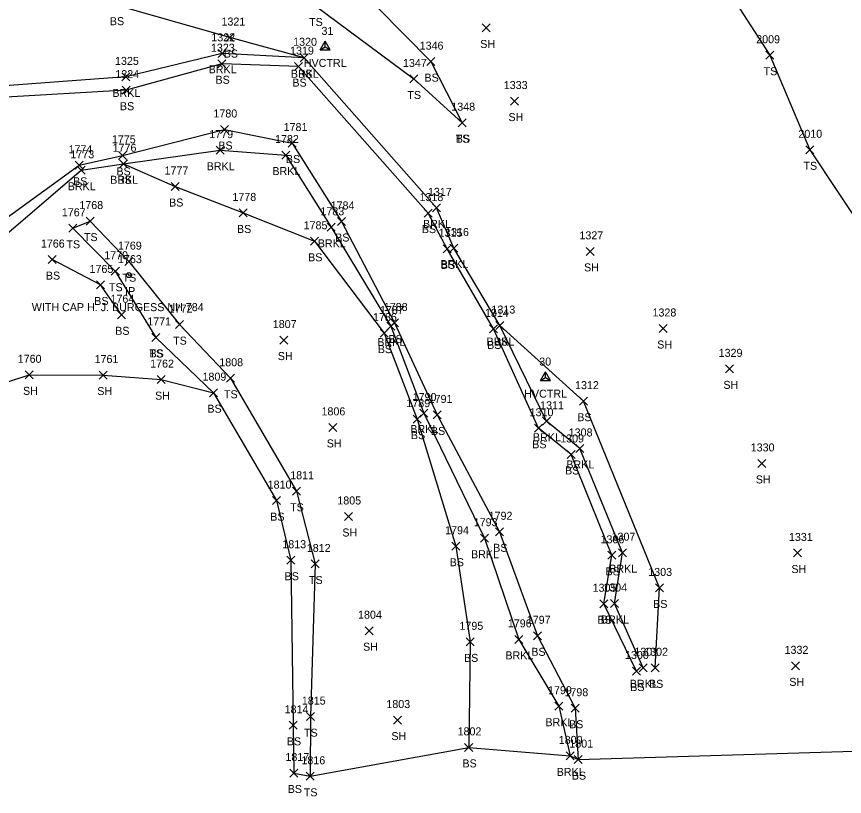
# Model space of a CAD drawing. Extents: x 1754529 to 1755810, y 621660 to 624656.
# Drawn here: x 1755214.3 to 1755421.2, y 623759.8 to 623954.6 of the extents above; entities that cross this region are included whole.
import ezdxf

# ---------------------------------------------------------------- set-up
doc = ezdxf.new("R2010")
doc.units = 0
for name, color, linetype in [('C_A', 7, 'Continuous'), ('C_I', 7, 'Continuous'), ('CPSM', 7, 'Continuous'), ('L_A', 7, 'Continuous'), ('L_I', 7, 'Continuous'), ('L_TIC', 7, 'Continuous'), ('LAWE', 7, 'Continuous'), ('LELB', 7, 'Continuous'), ('LSOGP', 7, 'Continuous'), ('M_A', 7, 'Continuous'), ('M_C', 7, 'Continuous'), ('M_I', 7, 'Continuous'), ('MPIR', 7, 'Continuous')]:
    doc.layers.add(name, color=color, linetype=linetype)

msp = doc.modelspace()

# ---------------------------------------------------------------- linework, layer by layer
at = {"layer": 'CPSM'}
for p, q in [((1755290.13, 623946.27), (1755291.38, 623948.44)), ((1755292.63, 623946.27), (1755291.38, 623948.44)), ((1755291.38, 623947), (1755291.38, 623948.44)), ((1755290.13, 623946.27), (1755291.38, 623947)), ((1755290.13, 623946.27), (1755292.63, 623946.27)), ((1755291.38, 623947), (1755291.38, 623947)), ((1755291.38, 623947), (1755292.63, 623946.27)), ((1755345.2, 623863.69), (1755346.45, 623865.86)), ((1755345.2, 623863.69), (1755346.45, 623864.41)), ((1755347.7, 623863.69), (1755346.45, 623865.86)), ((1755346.45, 623864.41), (1755346.45, 623865.86)), ((1755346.45, 623864.41), (1755346.45, 623864.41)), ((1755346.45, 623864.41), (1755347.7, 623863.69)), ((1755345.2, 623863.69), (1755347.7, 623863.69))]:
    msp.add_line(p, q, dxfattribs=at)
at = {"layer": 'L_TIC'}
for points in [[(1755330.68, 623950.74), (1755332.68, 623952.74)], [(1755332.68, 623950.74), (1755330.68, 623952.74)], [(1755266.63, 623948.34), (1755268.63, 623950.34)], [(1755268.63, 623948.34), (1755266.63, 623950.34)], [(1755264.65, 623944.4), (1755266.65, 623946.4)], [(1755266.65, 623944.4), (1755264.65, 623946.4)], [(1755285.2, 623943.29), (1755287.2, 623945.29)], [(1755287.2, 623943.29), (1755285.2, 623945.29)], [(1755285.2, 623943.29), (1755287.2, 623945.29)], [(1755287.2, 623943.29), (1755285.2, 623945.29)], [(1755401.54, 623943.92), (1755403.54, 623945.92)], [(1755403.54, 623943.92), (1755401.54, 623945.92)], [(1755264.57, 623941.8), (1755266.57, 623943.8)], [(1755266.57, 623941.8), (1755264.57, 623943.8)], [(1755283.78, 623941.09), (1755285.78, 623943.09)], [(1755285.78, 623941.09), (1755283.78, 623943.09)], [(1755316.78, 623942.33), (1755318.78, 623944.33)], [(1755318.78, 623942.33), (1755316.78, 623944.33)], [(1755240.6, 623938.51), (1755242.6, 623940.51)], [(1755242.6, 623938.51), (1755240.6, 623940.51)], [(1755312.55, 623938), (1755314.55, 623940)], [(1755314.55, 623938), (1755312.55, 623940)], [(1755240.68, 623935.2), (1755242.68, 623937.2)], [(1755242.68, 623935.2), (1755240.68, 623937.2)], [(1755337.73, 623932.48), (1755339.73, 623934.48)], [(1755339.73, 623932.48), (1755337.73, 623934.48)], [(1755324.62, 623927.08), (1755326.62, 623929.08)], [(1755326.62, 623927.08), (1755324.62, 623929.08)], [(1755324.62, 623927.08), (1755326.62, 623929.08)], [(1755326.62, 623927.08), (1755324.62, 623929.08)], [(1755265.28, 623925.38), (1755267.28, 623927.38)], [(1755267.28, 623925.38), (1755265.28, 623927.38)], [(1755264.16, 623920.22), (1755266.16, 623922.22)], [(1755266.16, 623920.22), (1755264.16, 623922.22)], [(1755282.17, 623922), (1755284.17, 623924)], [(1755284.17, 623922), (1755282.17, 623924)], [(1755411.5, 623920.31), (1755413.5, 623922.31)], [(1755413.5, 623920.31), (1755411.5, 623922.31)], [(1755239.82, 623918.92), (1755241.82, 623920.92)], [(1755241.82, 623918.92), (1755239.82, 623920.92)], [(1755280.59, 623919), (1755282.59, 623921)], [(1755282.59, 623919), (1755280.59, 623921)], [(1755228.99, 623916.44), (1755230.99, 623918.44)], [(1755230.99, 623916.44), (1755228.99, 623918.44)], [(1755240.06, 623916.82), (1755242.06, 623918.82)], [(1755242.06, 623916.82), (1755240.06, 623918.82)], [(1755240.06, 623916.82), (1755242.06, 623918.82)], [(1755242.06, 623916.82), (1755240.06, 623918.82)], [(1755229.46, 623915.2), (1755231.46, 623917.2)], [(1755231.46, 623915.2), (1755229.46, 623917.2)], [(1755252.98, 623911.14), (1755254.98, 623913.14)], [(1755254.98, 623911.14), (1755252.98, 623913.14)], [(1755318.21, 623905.81), (1755320.21, 623907.81)], [(1755320.21, 623905.81), (1755318.21, 623907.81)], [(1755269.94, 623904.54), (1755271.94, 623906.54)], [(1755271.94, 623904.54), (1755269.94, 623906.54)], [(1755316.12, 623904.5), (1755318.12, 623906.5)], [(1755318.12, 623904.5), (1755316.12, 623906.5)], [(1755231.74, 623902.51), (1755233.74, 623904.51)], [(1755233.74, 623902.51), (1755231.74, 623904.51)], [(1755294.47, 623902.4), (1755296.47, 623904.4)], [(1755296.47, 623902.4), (1755294.47, 623904.4)], [(1755227.36, 623900.7), (1755229.36, 623902.7)], [(1755229.36, 623900.7), (1755227.36, 623902.7)], [(1755227.36, 623900.7), (1755229.36, 623902.7)], [(1755229.36, 623900.7), (1755227.36, 623902.7)], [(1755291.93, 623900.95), (1755293.93, 623902.95)], [(1755293.93, 623900.95), (1755291.93, 623902.95)], [(1755287.72, 623897.46), (1755289.72, 623899.46)], [(1755289.72, 623897.46), (1755287.72, 623899.46)], [(1755320.88, 623895.58), (1755322.88, 623897.58)], [(1755322.88, 623895.58), (1755320.88, 623897.58)], [(1755322.56, 623895.77), (1755324.56, 623897.77)], [(1755324.56, 623895.77), (1755322.56, 623897.77)], [(1755356.63, 623894.94), (1755358.63, 623896.94)], [(1755358.63, 623894.94), (1755356.63, 623896.94)], [(1755222.19, 623892.89), (1755224.19, 623894.89)], [(1755224.19, 623892.89), (1755222.19, 623894.89)], [(1755241.39, 623892.38), (1755243.39, 623894.38)], [(1755243.39, 623892.38), (1755241.39, 623894.38)], [(1755237.99, 623889.98), (1755239.99, 623891.98)], [(1755239.99, 623889.98), (1755237.99, 623891.98)], [(1755234.28, 623886.55), (1755236.28, 623888.55)], [(1755236.28, 623886.55), (1755234.28, 623888.55)], [(1755239.52, 623879.1), (1755241.52, 623881.1)], [(1755241.52, 623879.1), (1755239.52, 623881.1)], [(1755307.77, 623877.06), (1755309.77, 623879.06)], [(1755309.77, 623877.06), (1755307.77, 623879.06)], [(1755254.02, 623876.65), (1755256.02, 623878.65)], [(1755256.02, 623876.65), (1755254.02, 623878.65)], [(1755306.79, 623876.29), (1755308.79, 623878.29)], [(1755308.79, 623876.29), (1755306.79, 623878.29)], [(1755332.45, 623875.59), (1755334.45, 623877.59)], [(1755334.45, 623875.59), (1755332.45, 623877.59)], [(1755334.09, 623876.41), (1755336.09, 623878.41)], [(1755336.09, 623876.41), (1755334.09, 623878.41)], [(1755334.09, 623876.41), (1755336.09, 623878.41)], [(1755336.09, 623876.41), (1755334.09, 623878.41)], [(1755374.89, 623875.68), (1755376.89, 623877.68)], [(1755376.89, 623875.68), (1755374.89, 623877.68)], [(1755248.09, 623873.44), (1755250.09, 623875.44)], [(1755250.09, 623873.44), (1755248.09, 623875.44)], [(1755248.09, 623873.44), (1755250.09, 623875.44)], [(1755250.09, 623873.44), (1755248.09, 623875.44)], [(1755280.1, 623872.79), (1755282.1, 623874.79)], [(1755282.1, 623872.79), (1755280.1, 623874.79)], [(1755305.12, 623874.52), (1755307.12, 623876.52)], [(1755307.12, 623874.52), (1755305.12, 623876.52)], [(1755391.43, 623865.6), (1755393.43, 623867.6)], [(1755393.43, 623865.6), (1755391.43, 623867.6)], [(1755216.43, 623864.11), (1755218.43, 623866.11)], [(1755218.43, 623864.11), (1755216.43, 623866.11)], [(1755234.99, 623864.05), (1755236.99, 623866.05)], [(1755236.99, 623864.05), (1755234.99, 623866.05)], [(1755249.43, 623862.91), (1755251.43, 623864.91)], [(1755251.43, 623862.91), (1755249.43, 623864.91)], [(1755266.73, 623863.25), (1755268.73, 623865.25)], [(1755268.73, 623863.25), (1755266.73, 623865.25)], [(1755262.55, 623859.65), (1755264.55, 623861.65)], [(1755264.55, 623859.65), (1755262.55, 623861.65)], [(1755354.97, 623857.53), (1755356.97, 623859.53)], [(1755356.97, 623857.53), (1755354.97, 623859.53)], [(1755315.06, 623854.57), (1755317.06, 623856.57)], [(1755317.06, 623854.57), (1755315.06, 623856.57)], [(1755318.4, 623854.09), (1755320.4, 623856.09)], [(1755320.4, 623854.09), (1755318.4, 623856.09)], [(1755313.4, 623853.04), (1755315.4, 623855.04)], [(1755315.4, 623853.04), (1755313.4, 623855.04)], [(1755345.68, 623852.51), (1755347.68, 623854.51)], [(1755347.68, 623852.51), (1755345.68, 623854.51)], [(1755292.32, 623850.98), (1755294.32, 623852.98)], [(1755294.32, 623850.98), (1755292.32, 623852.98)], [(1755343.71, 623850.76), (1755345.71, 623852.76)], [(1755345.71, 623850.76), (1755343.71, 623852.76)], [(1755351.91, 623844.22), (1755353.91, 623846.22)], [(1755353.91, 623844.22), (1755351.91, 623846.22)], [(1755354.03, 623845.72), (1755356.03, 623847.72)], [(1755356.03, 623845.72), (1755354.03, 623847.72)], [(1755399.52, 623841.98), (1755401.52, 623843.98)], [(1755401.52, 623841.98), (1755399.52, 623843.98)], [(1755283.24, 623835.03), (1755285.24, 623837.03)], [(1755285.24, 623835.03), (1755283.24, 623837.03)], [(1755278.26, 623832.69), (1755280.26, 623834.69)], [(1755280.26, 623832.69), (1755278.26, 623834.69)], [(1755296.23, 623828.73), (1755298.23, 623830.73)], [(1755298.23, 623828.73), (1755296.23, 623830.73)], [(1755330.23, 623823.3), (1755332.23, 623825.3)], [(1755332.23, 623823.3), (1755330.23, 623825.3)], [(1755333.96, 623824.91), (1755335.96, 623826.91)], [(1755335.96, 623824.91), (1755333.96, 623826.91)], [(1755323.08, 623821.3), (1755325.08, 623823.3)], [(1755325.08, 623821.3), (1755323.08, 623823.3)], [(1755362.04, 623819.03), (1755364.04, 623821.03)], [(1755364.04, 623819.03), (1755362.04, 623821.03)], [(1755364.74, 623819.69), (1755366.74, 623821.69)], [(1755366.74, 623819.69), (1755364.74, 623821.69)], [(1755408.41, 623819.61), (1755410.41, 623821.61)], [(1755410.41, 623819.61), (1755408.41, 623821.61)], [(1755281.84, 623817.8), (1755283.84, 623819.8)], [(1755283.84, 623817.8), (1755281.84, 623819.8)], [(1755287.95, 623816.87), (1755289.95, 623818.87)], [(1755289.95, 623816.87), (1755287.95, 623818.87)], [(1755373.92, 623810.88), (1755375.92, 623812.88)], [(1755375.92, 623810.88), (1755373.92, 623812.88)], [(1755360.01, 623806.93), (1755362.01, 623808.93)], [(1755362.01, 623806.93), (1755360.01, 623808.93)], [(1755362.68, 623807), (1755364.68, 623809)], [(1755364.68, 623807), (1755362.68, 623809)], [(1755301.4, 623800.2), (1755303.4, 623802.2)], [(1755303.4, 623800.2), (1755301.4, 623802.2)], [(1755343.48, 623798.93), (1755345.48, 623800.93)], [(1755345.48, 623798.93), (1755343.48, 623800.93)], [(1755326.66, 623797.42), (1755328.66, 623799.42)], [(1755328.66, 623797.42), (1755326.66, 623799.42)], [(1755338.8, 623798.04), (1755340.8, 623800.04)], [(1755340.8, 623798.04), (1755338.8, 623800.04)], [(1755368.19, 623790.13), (1755370.19, 623792.13)], [(1755370.19, 623790.13), (1755368.19, 623792.13)], [(1755369.87, 623790.95), (1755371.87, 623792.95)], [(1755371.87, 623790.95), (1755369.87, 623792.95)], [(1755372.89, 623790.94), (1755374.89, 623792.94)], [(1755374.89, 623790.94), (1755372.89, 623792.94)], [(1755407.89, 623791.42), (1755409.89, 623793.42)], [(1755409.89, 623791.42), (1755407.89, 623793.42)], [(1755348.8, 623781.35), (1755350.8, 623783.35)], [(1755350.8, 623781.35), (1755348.8, 623783.35)], [(1755352.9, 623780.84), (1755354.9, 623782.84)], [(1755354.9, 623780.84), (1755352.9, 623782.84)], [(1755286.72, 623778.74), (1755288.72, 623780.74)], [(1755288.72, 623778.74), (1755286.72, 623780.74)], [(1755308.48, 623777.88), (1755310.48, 623779.88)], [(1755310.48, 623777.88), (1755308.48, 623779.88)], [(1755282.41, 623776.57), (1755284.41, 623778.57)], [(1755284.41, 623776.57), (1755282.41, 623778.57)], [(1755326.27, 623771.06), (1755328.27, 623773.06)], [(1755328.27, 623771.06), (1755326.27, 623773.06)], [(1755351.63, 623768.93), (1755353.63, 623770.93)], [(1755353.63, 623768.93), (1755351.63, 623770.93)], [(1755353.61, 623768.01), (1755355.61, 623770.01)], [(1755355.61, 623768.01), (1755353.61, 623770.01)], [(1755282.62, 623764.66), (1755284.62, 623766.66)], [(1755284.62, 623764.66), (1755282.62, 623766.66)], [(1755286.66, 623763.84), (1755288.66, 623765.84)], [(1755288.66, 623763.84), (1755286.66, 623765.84)]]:
    msp.add_lwpolyline(points, dxfattribs=at)
at = {"layer": 'LAWE'}
for points in [[(1755370.87, 623791.95), (1755363.68, 623808), (1755365.74, 623820.69), (1755355.03, 623846.72), (1755346.68, 623853.51), (1755335.09, 623877.41), (1755323.56, 623896.77), (1755319.21, 623906.81), (1755286.2, 623944.29), (1755265.65, 623945.4), (1755241.6, 623939.51), (1755210.27, 623937.23), (1755179.93, 623958.52)], [(1755204.82, 623894.29), (1755230.46, 623916.2), (1755241.06, 623917.82), (1755265.16, 623921.22), (1755281.59, 623920), (1755292.93, 623901.95), (1755307.79, 623877.29), (1755316.06, 623855.57), (1755331.23, 623824.3), (1755339.8, 623799.04), (1755349.8, 623782.35), (1755352.63, 623769.93)]]:
    msp.add_lwpolyline(points, dxfattribs=at)
at = {"layer": 'LELB'}
for points in [[(1755283.63, 624321.58), (1755261.89, 624310.21), (1755241.28, 624298.92), (1755225.63, 624290.24), (1755219.57, 624277.64), (1755236.29, 624268.09), (1755239.17, 624251.56), (1755235.61, 624235.54), (1755253.41, 624214.52), (1755275.93, 624188.95), (1755280.26, 624179.83), (1755294.83, 624178.69), (1755307.15, 624169.54), (1755309.03, 624155.09), (1755307.67, 624133.57), (1755296.24, 624106.15), (1755299.26, 624064.9), (1755318.78, 624037.89), (1755344, 624017.13), (1755370, 623994.13), (1755389.34, 623965.32), (1755402.54, 623944.92), (1755412.5, 623921.31), (1755426.67, 623899.96)], [(1755286.2, 623944.29), (1755267.63, 623949.34), (1755239.18, 623957.43), (1755232.04, 623971.1), (1755221.75, 623997.22), (1755207.57, 624028.22), (1755193.15, 624052.21), (1755209.59, 624065.41), (1755204.71, 624097.4), (1755197.92, 624122.33)], [(1755249.6, 623996.64), (1755238.46, 623980.5), (1755248.16, 623968.47), (1755260.84, 623963.41), (1755288.99, 623957.23), (1755313.55, 623939), (1755325.62, 623928.08)], [(1755249.6, 623996.64), (1755264.38, 623977.8), (1755286.06, 623972.14), (1755297.89, 623963.61), (1755317.78, 623943.33), (1755325.62, 623928.08)], [(1755369.19, 623791.13), (1755361.01, 623807.93), (1755363.04, 623820.03), (1755352.91, 623845.22), (1755344.71, 623851.76), (1755333.45, 623876.59), (1755321.88, 623896.58), (1755317.12, 623905.5), (1755284.78, 623942.09), (1755265.57, 623942.8), (1755241.68, 623936.2), (1755210.26, 623934.38)], [(1755204.31, 623898.91), (1755229.99, 623917.44), (1755240.82, 623919.92), (1755266.28, 623926.38), (1755283.17, 623923), (1755295.47, 623903.4), (1755308.77, 623878.06), (1755319.4, 623855.09), (1755334.96, 623825.91), (1755344.48, 623799.93), (1755353.9, 623781.84), (1755354.61, 623769.01)], [(1755241.06, 623917.82), (1755253.98, 623912.14), (1755270.94, 623905.54), (1755288.72, 623898.46), (1755306.12, 623875.52), (1755314.4, 623854.04), (1755324.08, 623822.3), (1755327.66, 623798.42), (1755327.27, 623772.06)], [(1755228.36, 623901.7), (1755232.74, 623903.51), (1755242.39, 623893.38), (1755255.02, 623877.65), (1755267.73, 623864.25), (1755284.24, 623836.03), (1755288.95, 623817.87), (1755287.72, 623779.74), (1755287.66, 623764.84)], [(1755228.36, 623901.7), (1755238.99, 623890.98), (1755249.09, 623874.44)], [(1755240.52, 623880.1), (1755235.28, 623887.55), (1755223.19, 623893.89)], [(1755373.89, 623791.94), (1755374.92, 623811.88), (1755355.97, 623858.53), (1755335.09, 623877.41)], [(1755249.09, 623874.44), (1755263.55, 623860.65), (1755279.26, 623833.69), (1755282.84, 623818.8), (1755283.41, 623777.57), (1755283.62, 623765.66)]]:
    msp.add_lwpolyline(points, dxfattribs=at)
at = {"layer": 'LSOGP'}
msp.add_lwpolyline([(1755004.07, 623910.86), (1755037.03, 623891.65), (1755051.38, 623882.08), (1755070.03, 623866.74), (1755086.65, 623861.82), (1755098.54, 623857.57), (1755139.32, 623863.34), (1755161.91, 623859.08), (1755179.26, 623858.35), (1755194.19, 623862.7), (1755207.96, 623861.99), (1755217.43, 623865.11), (1755235.99, 623865.05), (1755250.43, 623863.91), (1755263.55, 623860.65), (1755279.26, 623833.69), (1755282.84, 623818.8), (1755283.41, 623777.57), (1755283.62, 623765.66), (1755287.66, 623764.84), (1755327.27, 623772.06), (1755352.63, 623769.93), (1755354.61, 623769.01), (1755434.62, 623771.42)], dxfattribs=at)
at = {"layer": 'MPIR'}
for radius in [0.625, 0.0833]:
    msp.add_circle((1755242.39, 623890.01), radius, dxfattribs=at)

# ---------------------------------------------------------------- texts
at = {"layer": 'C_A'}
for p in [(1755286.08, 623942), (1755341.15, 623859.41)]:
    msp.add_text('HVCTRL', height=2, dxfattribs=at).set_placement(p)
at = {"layer": 'C_I'}
for s, p in [('31', (1755290.49, 623950)), ('30', (1755344.9, 623867.41))]:
    msp.add_text(s, height=2, dxfattribs=at).set_placement(p)
at = {"layer": 'L_A'}
for s, p in [('BS', (1755237.62, 623952.43)), ('TS', (1755287.4, 623952.23)), ('SH', (1755330.16, 623946.74)), ('BS', (1755266.07, 623944.34)), ('BRKL', (1755262.3, 623940.4)), ('BRKL', (1755282.84, 623939.29)), ('BS', (1755284.64, 623939.29)), ('TS', (1755400.95, 623939.92)), ('BS', (1755264.01, 623937.8)), ('BS', (1755283.22, 623937.09)), ('BS', (1755316.22, 623938.33)), ('BRKL', (1755238.25, 623934.51)), ('TS', (1755311.96, 623934)), ('BS', (1755240.13, 623931.2)), ('SH', (1755337.22, 623928.48)), ('TS', (1755324.03, 623923.08)), ('BS', (1755324.06, 623923.08)), ('BS', (1755264.72, 623921.38)), ('BRKL', (1755261.81, 623916.22)), ('BS', (1755281.61, 623918)), ('TS', (1755410.91, 623916.31)), ('BS', (1755239.26, 623914.92)), ('BRKL', (1755278.23, 623915)), ('BS', (1755228.43, 623912.44)), ('BRKL', (1755237.7, 623912.82)), ('BS', (1755239.5, 623912.82)), ('BRKL', (1755227.1, 623911.2)), ('BS', (1755252.42, 623907.14)), ('BRKL', (1755315.86, 623901.81)), ('BS', (1755269.38, 623900.54)), ('BS', (1755315.56, 623900.5)), ('TS', (1755231.15, 623898.51)), ('BS', (1755293.91, 623898.4)), ('TS', (1755226.77, 623896.7)), ('TS', (1755226.77, 623896.7)), ('BRKL', (1755289.57, 623896.95)), ('BS', (1755287.16, 623893.46)), ('BRKL', (1755320.21, 623891.77)), ('BS', (1755320.32, 623891.58)), ('SH', (1755356.12, 623890.94)), ('BS', (1755221.63, 623888.89)), ('TS', (1755240.8, 623888.38)), ('TS', (1755237.4, 623885.98)), ('BS', (1755233.72, 623882.55)), ('BS', (1755238.96, 623875.1)), ('TS', (1755253.43, 623872.65)), ('BS', (1755307.21, 623873.06)), ('BRKL', (1755304.44, 623872.29)), ('BRKL', (1755331.73, 623872.41)), ('BS', (1755331.89, 623871.59)), ('BS', (1755333.53, 623872.41)), ('SH', (1755374.38, 623871.68)), ('TS', (1755247.5, 623869.44)), ('BS', (1755247.53, 623869.44)), ('SH', (1755279.59, 623868.79)), ('BS', (1755304.56, 623870.52)), ('SH', (1755390.92, 623861.6)), ('SH', (1755215.92, 623860.11)), ('SH', (1755234.48, 623860.05)), ('SH', (1755248.92, 623858.91)), ('TS', (1755266.14, 623859.25)), ('BS', (1755261.99, 623855.65)), ('BS', (1755354.41, 623853.53)), ('BRKL', (1755312.7, 623850.57)), ('BS', (1755317.84, 623850.09)), ('BS', (1755312.84, 623849.04)), ('BRKL', (1755343.33, 623848.51)), ('SH', (1755291.81, 623846.98)), ('BS', (1755343.15, 623846.76)), ('BRKL', (1755351.67, 623841.72)), ('BS', (1755351.35, 623840.22)), ('SH', (1755399.01, 623837.98)), ('TS', (1755282.65, 623831.03)), ('BS', (1755277.7, 623828.69)), ('SH', (1755295.71, 623824.73)), ('BS', (1755333.4, 623820.91)), ('BRKL', (1755327.87, 623819.3)), ('BS', (1755322.52, 623817.3)), ('BS', (1755361.48, 623815.03)), ('BRKL', (1755362.39, 623815.69)), ('SH', (1755407.9, 623815.61)), ('BS', (1755281.28, 623813.8)), ('TS', (1755287.36, 623812.87)), ('BS', (1755373.36, 623806.88)), ('BS', (1755359.45, 623802.93)), ('BRKL', (1755360.32, 623803)), ('SH', (1755300.89, 623796.2)), ('BRKL', (1755336.45, 623794.04)), ('BS', (1755342.92, 623794.93)), ('BS', (1755326.1, 623793.42)), ('BRKL', (1755367.52, 623786.95)), ('BS', (1755367.63, 623786.13)), ('BS', (1755372.33, 623786.94)), ('SH', (1755407.38, 623787.42)), ('BRKL', (1755346.45, 623777.35)), ('BS', (1755352.34, 623776.84)), ('TS', (1755286.13, 623774.74)), ('SH', (1755307.97, 623773.88)), ('BS', (1755281.85, 623772.57)), ('BS', (1755325.71, 623767.06)), ('BRKL', (1755349.27, 623764.93)), ('BS', (1755353.05, 623764.01)), ('BS', (1755282.06, 623760.66)), ('TS', (1755286.07, 623759.84))]:
    msp.add_text(s, height=2, dxfattribs=at).set_placement(p)
at = {"layer": 'L_I'}
for s, p in [('1321', (1755265.51, 623952.34)), ('1322', (1755262.96, 623948.4)), ('1320', (1755283.42, 623947.29)), ('1320', (1755283.42, 623947.29)), ('2009', (1755399.11, 623947.92)), ('1323', (1755262.88, 623945.8)), ('1319', (1755282.65, 623945.09)), ('1346', (1755315.03, 623946.33)), ('1325', (1755238.91, 623942.51)), ('1347', (1755310.86, 623942)), ('1324', (1755238.99, 623939.2)), ('1333', (1755336.04, 623936.48)), ('1348', (1755322.93, 623931.08)), ('1348', (1755322.93, 623931.08)), ('1780', (1755263.5, 623929.38)), ('1781', (1755281.04, 623926)), ('2010', (1755409.65, 623924.31)), ('1775', (1755238.13, 623922.92)), ('1779', (1755262.46, 623924.22)), ('1782', (1755278.89, 623923)), ('1774', (1755227.29, 623920.44)), ('1776', (1755238.31, 623920.82)), ('1776', (1755238.31, 623920.82)), ('1773', (1755227.76, 623919.2)), ('1777', (1755251.28, 623915.14)), ('1778', (1755268.24, 623908.54)), ('1318', (1755314.99, 623908.5)), ('1317', (1755317.09, 623909.81)), ('1768', (1755230, 623906.51)), ('1784', (1755292.78, 623906.4)), ('1767', (1755225.62, 623904.7)), ('1767', (1755225.62, 623904.7)), ('1783', (1755290.23, 623904.95)), ('1785', (1755286.03, 623901.46)), ('1315', (1755319.76, 623899.58)), ('1316', (1755321.38, 623899.77)), ('1327', (1755354.94, 623898.94)), ('1766', (1755220.39, 623896.89)), ('1769', (1755239.64, 623896.38)), ('1770', (1755236.21, 623893.98)), ('1765', (1755232.54, 623890.55)), ('1764', (1755237.78, 623883.1)), ('1788', (1755306.07, 623881.06)), ('1772', (1755252.33, 623880.65)), ('1787', (1755305.1, 623880.29)), ('1314', (1755331.33, 623879.59)), ('1313', (1755332.96, 623880.41)), ('1313', (1755332.96, 623880.41)), ('1328', (1755373.2, 623879.68)), ('1771', (1755246.97, 623877.44)), ('1771', (1755246.97, 623877.44)), ('1807', (1755278.33, 623876.79)), ('1786', (1755303.37, 623878.52)), ('1329', (1755389.73, 623869.6)), ('1760', (1755214.6, 623868.11)), ('1761', (1755233.81, 623868.05)), ('1762', (1755247.69, 623866.91)), ('1808', (1755264.96, 623867.25)), ('1809', (1755260.77, 623863.65)), ('1312', (1755353.85, 623861.53)), ('1790', (1755313.28, 623858.57)), ('1789', (1755311.7, 623857.04)), ('1791', (1755317.27, 623858.09)), ('1311', (1755345.12, 623856.51)), ('1806', (1755290.5, 623854.98)), ('1310', (1755342.5, 623854.76)), ('1309', (1755350.13, 623848.22)), ('1308', (1755352.26, 623849.72)), ('1330', (1755397.74, 623845.98)), ('1811', (1755282.68, 623839.03)), ('1810', (1755277.05, 623836.69)), ('1805', (1755294.45, 623832.73)), ('1793', (1755328.53, 623827.3)), ('1792', (1755332.26, 623828.91)), ('1794', (1755321.39, 623825.3)), ('1306', (1755360.22, 623823.03)), ('1307', (1755362.97, 623823.69)), ('1331', (1755407.29, 623823.61)), ('1813', (1755280.71, 623821.8)), ('1812', (1755286.82, 623820.87)), ('1303', (1755372.14, 623814.88)), ('1305', (1755358.24, 623810.93)), ('1304', (1755360.9, 623811)), ('1804', (1755299.63, 623804.2)), ('1797', (1755341.79, 623802.93)), ('1795', (1755324.97, 623801.42)), ('1796', (1755337.05, 623802.04)), ('1300', (1755366.33, 623794.13)), ('1301', (1755368.67, 623794.95)), ('1302', (1755371.12, 623794.94)), ('1332', (1755406.2, 623795.42)), ('1799', (1755347.1, 623785.35)), ('1798', (1755351.2, 623784.84)), ('1815', (1755285.59, 623782.74)), ('1803', (1755306.71, 623781.88)), ('1814', (1755281.29, 623780.57)), ('1802', (1755324.5, 623775.06)), ('1800', (1755349.77, 623772.93)), ('1801', (1755352.41, 623772.01)), ('1817', (1755281.49, 623768.66)), ('1816', (1755285.48, 623767.84))]:
    msp.add_text(s, height=2, dxfattribs=at).set_placement(p)
at = {"layer": 'M_A'}
msp.add_text('IP', height=2, dxfattribs=at).set_placement((1755241.44, 623885.01))
at = {"layer": 'M_C'}
msp.add_text('WITH CAP H. J. BURGESS NH 784', height=2, dxfattribs=at).set_placement((1755218.11, 623881.01))
at = {"layer": 'M_I'}
msp.add_text('1763', height=2, dxfattribs=at).set_placement((1755239.65, 623893.01))

doc.saveas('drawing.dxf')
